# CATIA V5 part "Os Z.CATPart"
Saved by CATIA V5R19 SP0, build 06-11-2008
Part number: Os Z
Bounding box of the stored display mesh (mm): x 0 to 432.781, y -78.274 to 401.726, z -124.001 to 385.999
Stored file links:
  E:\Podręcznik\catia\Machine\Os Z.CATPart
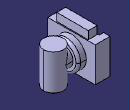
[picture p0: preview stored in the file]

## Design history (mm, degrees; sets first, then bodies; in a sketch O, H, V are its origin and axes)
Body1 (main body)
  Sketch1 on yz-plane, origin (0, 0, 0), H (0, 1, 0), V (0, 0, 1)
    line L1 (-78.2737, 305.9989) -> (401.7263, 305.9989)
    line L2 (401.7263, 305.9989) -> (401.7263, -44.0011)
    line L3 (401.7263, -44.0011) -> (-78.2737, -44.0011)
    line L4 (-78.2737, -44.0011) -> (-78.2737, 305.9989)
    length L3 = 480
    length L2 = 350
    horizontal: L1 H, L3 H
    vertical: L2 V, L4 V
  Pad1: profile Sketch1, direction (1, 0, 0), length 150
  Sketch2 on face of Pad1 from Sketch1.L1, origin (0, 0, 305.9989), H (1, 0, 0), V (0, 1, 0)
    line L1 (50, 321.7263) -> (140, 321.7263)
    line L2 (140, 321.7263) -> (140, 1.7263)
    line L3 (140, 1.7263) -> (50, 1.7263)
    line L4 (50, 1.7263) -> (50, 321.7263)
    reference projected line E1 (0, 401.7263) -> (120, 401.7263) from edge [face of Pad1 from Sketch1.L1 | face of Pad1 from Sketch1.L2]
    reference projected line E2 (150, 336.7263) -> (150, -13.2737) from edge [face of Pad1 from Sketch1.L1 | end face of Pad1]
    reference projected line E3 (0, -78.2737) -> (150, -78.2737) from edge [face of Pad1 from Sketch1.L4 | face of Pad1 from Sketch1.L1]
    distance L1 E1 = 80
    length L1 = 90
    distance L2 E2 = 10
    distance L3 E3 = 80
    horizontal: L1 H
    vertical: L2 V, L4 V
  Pad2: profile Sketch2, direction (0, 0, 1), length 80
  Sketch3 on end face of Pad1, origin (150, 0, 0), H (0, 1, 0), V (0, 0, 1)
    circle A1 centre (161.7263, 130.9989) radius 148.369
    point P1 (161.7263, 130.9989)
    reference projected line E1 (401.7263, -44.0011) -> (401.7263, 305.9989) from edge [face of Pad1 from Sketch1.L2 | end face of Pad1]
    reference projected line E2 (336.7263, 305.9989) -> (-13.2737, 305.9989) from edge [face of Pad1 from Sketch1.L1 | end face of Pad1]
    distance P1 E1 = 240
    distance P1 E2 = 175
  Pad3: profile Sketch3, direction (1, 0, 0), length 80
  Fillet1: radius 25, on edge [face of Pad3 from Sketch3.A1 | end face of Pad3]
  Sketch4 on end face of Pad3, origin (230, 0, 0), H (0, 1, 0), V (0, 0, 1)
    circle A1 centre (161.7263, 130.9989) radius 94.8116
    reference projected circle E1 centre (161.7263, 130.9989) radius 123.369 from edge [face of Fillet1 | end face of Pad3]
    concentricity: A1 E1
  Pad4: profile Sketch4, direction (1, 0, 0), length 80
  Plane1: type Offset, Offset 20, RefPlane face of Pad1 from Sketch1.L1
  Sketch5 on Plane1, origin (0, 0, 285.9989), H (1, 0, 0), V (0, -1, 0)
    circle A1 centre (332.7812, -161.7263) radius 100
    point P1 (332.7812, -161.7263)
    axis line L1 (-41.4281, -161.7263) -> (294.8199, -161.7263)
    reference projected line E1 (0, 78.2737) -> (120, 78.2737) from edge [face of Pad1 from Sketch1.L3 | face of Pad1 from Sketch1.L4]
    distance L1 E1 = 240
    radius A1 = 100
    coincidence: P1 L1
  Pad5: profile Sketch5, direction (0, 0, -1), length 360
  Sketch6 on end face of Pad5, origin (0, 0, -74.0011), H (1, 0, 0), V (0, -1, 0)
    circle A1 centre (332.7812, -161.7263) radius 32.1014
    reference projected circle E1 centre (332.7812, -161.7263) radius 100 from edge [face of Pad5 from Sketch5.A1 | end face of Pad5]
    concentricity: A1 E1
  Pad6: profile Sketch6, direction (0, 0, -1), length 50
  Sketch7 on start face of Pad1, origin (0, 0, 0), H (0, -1, 0), V (0, 0, 1)
    line L1 (-336.7263, 320.6074) -> (13.2737, 320.6074)
    line L2 (13.2737, 320.6074) -> (13.2737, -138.4575)
    line L3 (13.2737, -138.4575) -> (-336.7263, -138.4575)
    line L4 (-336.7263, -138.4575) -> (-336.7263, 320.6074)
    reference projected line E1 (-401.7263, -44.0011) -> (-401.7263, 305.9989) from edge [start face of Pad1 | face of Pad1 from Sketch1.L2]
    length L3 = 350
    distance L4 E1 = 65
    horizontal: L1 H, L3 H
    vertical: L2 V, L4 V
  Pocket1: profile Sketch7, direction (1, 0, 0), length 45
  DatumCurve1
